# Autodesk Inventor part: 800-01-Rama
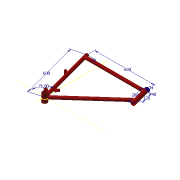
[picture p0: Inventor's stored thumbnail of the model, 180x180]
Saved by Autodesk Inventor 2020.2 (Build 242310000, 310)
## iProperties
Created: 2014-12
Part Number: 800-01-Rama
Material: Aluminium 6061
Document SubType Name: Modeling
Designer: F.Stasiak
Density: 2.7 g/cm^3
Appearance: Czerwona
Catalog Web Link: www.expertbooks.pl
Manager: www.cadconsulting.pl
Company: Fabian Stasiak CAD Consulting
Author: F.Stasiak
Subject: Zbiór ćwiczeń. Autodesk Inventor 2020. Kurs Professional
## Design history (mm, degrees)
sketch "Szkic1"
  geometry: C1 r 25 at (0, 0); C2 r 21 at (0, 0); 1 further point
  constraints: 2 centre point, 2 coincident
  dimensions: "d0" = 50 diameter of C1; "d35" = 42 diameter of C2
extrude "Wyciągnięcie proste1" new body sketch "Szkic1" stored distance "d2" = 80; taper "d3" = 0 deg
sketch "Szkic2"
  geometry: L1 (-6.47, 24.148)-(-155.291, 579.555); L2 (18.616, 16.686)-(483.805, 433.644); L3 (-147.253, 549.555)-(452.747, 549.555); L4 (444.709, 579.555)-(496.472, 386.37); L5 (-285.644, 0)-(626.825, 0) reference; A1 r 25 centre (0, 0) between (-6.47, 24.148) and (18.616, 16.686) reference; 1 further point
  constraints: 8 end point, 5 point on line, 2 point on circle, 1 horizontal, 1 horizontal alignment, 1 parallel
  dimensions: "d6" = 200 distance of L4.start L4.end; "d7" = 600 distance of L1.end point (0, 0); "d10" = 30 distance from line of L3 L1.end; "d11" = 75 deg angle of L1 L5; "d12" = 120 distance of L3.end L2.end; "d13" = 600 distance of L4.start L1.end
node "Płaszczyzna konstrukcyjna1"
sketch "Szkic3"
  geometry: C1 r 15 at (0, 0); C2 r 12 at (0, 0); 1 further point
  constraints: 2 centre point, 2 coincident
  dimensions: "d14" = 30 diameter of C1; "d29" = 24 diameter of C2
extrude "Wyciągnięcie proste2" join sketch "Szkic3" stored distance "d15" = 10; taper "d16" = 0 deg
node "Płaszczyzna konstrukcyjna2"
sketch "Szkic4"
  geometry: C1 r 15 at (0, 0); C2 r 12 at (0, 0); 4 further points
  constraints: 2 centre point, 2 coincident
  dimensions: "d17" = 30 diameter of C1; "d30" = 24 diameter of C2
extrude "Wyciągnięcie proste3" join sketch "Szkic4" stored distance "d18" = 10; taper "d19" = 0 deg
node "Płaszczyzna konstrukcyjna3"
sketch "Szkic5"
  geometry: C1 r 15 at (0, 0); C2 r 12 at (0, 0); 4 further points
  constraints: 2 centre point, 2 coincident
  dimensions: "d20" = 30 diameter of C1; "d31" = 24 diameter of C2
extrude "Wyciągnięcie proste4" join sketch "Szkic5" stored distance "d21" = 10; taper "d22" = 0 deg
node "Płaszczyzna konstrukcyjna4"
sketch "Szkic6"
  geometry: C1 r 20 at (0, 0); C2 r 17 at (0, 0); 4 further points
  constraints: 2 centre point, 2 coincident
  dimensions: "d23" = 40 diameter of C1; "d32" = 34 diameter of C2
extrude "Wyciągnięcie proste5" join sketch "Szkic6" distance "d24" = 200; taper "d25" = 0 deg
fillet "Zaokrąglenie1" dims "d27" = 5
fillet "Zaokrąglenie2" dims "d28" = 5
extrude "Wyciągnięcie proste6" cut sketch "Szkic6" extent not by distance; stored distance "d33" = 200; taper "d34" = 0 deg
extrude "Wyciągnięcie proste7" cut sketch "Szkic1" extent not by distance; stored distance "d36" = 200; taper "d37" = 0 deg
sketch "Szkic7"
  geometry: C1 r 15 at (-45, 55); 1 further point
  constraints: 1 centre point
  dimensions: "d38" = 30 diameter of C1; "d39" = 45 horizontal distance of point (0, 0) C1.centre; "d40" = 55 vertical distance of C1.centre point (0, 0)
extrude "Wyciągnięcie proste8" join sketch "Szkic7" stored distance "d41" = 45; taper "d42" = 0 deg
fillet "Zaokrąglenie3" dims "d43" = 5
sketch "Szkic8"
  geometry: C1 r 15 at (0, 0) reference; C2 r 10 at (0, 0); 1 further point
  constraints: 1 centre point, 1 coincident
  dimensions: "d44" = 20 diameter of C2
extrude "Wyciągnięcie proste9" cut sketch "Szkic8" extent not by distance; stored distance "d45" = 55; taper "d46" = 0 deg
sketch "Szkic9"
  geometry: C1 r 10 at (-112, 320); 1 further point
  constraints: 1 centre point
  dimensions: "d47" = 20 diameter of C1; "d48" = 112 horizontal distance of point (0, 0) C1.centre; "d49" = 320 vertical distance of C1.centre point (0, 0)
extrude "Wyciągnięcie proste10" join sketch "Szkic9" stored distance "d50" = 40; taper "d51" = 0 deg
fillet "Zaokrąglenie4" dims "d52" = 5
sketch "Szkic10"
  geometry: C1 r 10 at (0, 0) reference; C2 r 6 at (0, 0); 1 further point
  constraints: 1 centre point, 1 coincident
  dimensions: "d53" = 12 diameter of C2
extrude "Wyciągnięcie proste11" cut sketch "Szkic10" extent not by distance; stored distance "d54" = 40; taper "d55" = 0 deg
sketch "Szkic11"
  geometry: L1 (-140.803, 583.438)-(6.063, 35.327) reference; L2 (-22.41, 130)-(10.59, 130); L3 (10.59, 130)-(10.59, 100); L4 (10.59, 100)-(-14.372, 100); L5 (-143.7, 582.661)-(5.915, 24.29) reference; 1 further point
  constraints: 6 end point, 2 perpendicular, 2 point on line, 1 horizontal
  dimensions: "d57" = 30 distance of L2.end L3.end; "d58" = 130 distance from line of point (0, 0) L2; "d59" = 33 distance of L2.start L2.end
extrude "Wyciągnięcie proste12" join sketch "Szkic11" stored distance "d60" = 12; taper "d61" = 0 deg
sketch "Szkic12"
  geometry: L1 (-20.601, 130)-(10.59, 130) reference; L2 (10.59, 130)-(10.59, 100) reference; C1 r 10 at (10.59, 130); C2 r 5 at (10.59, 130); 1 further point
  constraints: 2 centre point, 2 coincident
  dimensions: "d62" = 20 diameter of C1; "d63" = 10 diameter of C2
extrude "Wyciągnięcie proste13" join sketch "Szkic12" stored distance "d64" = 15; taper "d65" = 0 deg
fillet "Zaokrąglenie5" dims "d66" = 10
sketch "Szkic13"
  geometry: C1 r 10 at (0, 0) reference; C2 r 6 at (0, 0); 1 further point
  constraints: 1 centre point, 1 coincident
  dimensions: "d67" = 12 diameter of C2
extrude "Wyciągnięcie proste14" cut sketch "Szkic13" extent not by distance; stored distance "d68" = 15; taper "d69" = 0 deg
node "Bryła1"
node "Pętla rzutowana1"
